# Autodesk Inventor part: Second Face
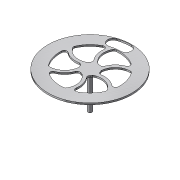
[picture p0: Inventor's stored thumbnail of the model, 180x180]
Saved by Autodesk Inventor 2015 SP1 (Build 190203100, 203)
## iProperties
Created: 2015-01
Part Number: Second Face
Material: Generic
Document SubType Name: Modeling
Designer: Steve Brooks
Density: 1 g/cm^3
Appearance: Machined - Aluminum
Author: Steve Brooks
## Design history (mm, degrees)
sketch "Sketch1"
  geometry: C1 r 7.5 at (203, 89); 1 further point
  constraints: 1 centre point
  dimensions: "d0" = 15 diameter of C1
extrude "Extrusion1" new body sketch "Sketch1" distance "d1" = 130; taper "d2" = 0 deg
sketch "Sketch2"
  geometry: C1 r 7.5 at (0, 0) reference; C2 r 155 at (0, 0); 1 further point
  constraints: 1 centre point, 1 coincident
  dimensions: "d3" = 310 diameter of C2
extrude "Extrusion2" join sketch "Sketch2" distance "d4" = 6; taper "d5" = 0 deg
sketch "Sketch3"
  geometry: L1 (0, 0)-(0, 133); L2 (0, 0)-(-41.099, 126.491); C1 r 155 at (0, 0) reference; C2 r 7.5 at (0, 0) reference; A1 r 20 centre (0, 133) between (0, 113) and (0, 153); A2 r 20 centre (-41.099, 126.491) between (-47.28, 145.512) and (-34.919, 107.469); A3 r 153 centre (0, 0) between (0, 153) and (-47.28, 145.512); A4 r 113 centre (0, 0) between (0, 113) and (-34.919, 107.469); 1 further point
  constraints: 8 point on circle, 4 centre point, 4 end point, 2 coincident, 2 point on line, 1 equal length, 1 vertical
  dimensions: "d8" = 40 diameter of A1; "d9" = 133 distance of C1.centre L1.end; "d19" = 40 diameter of A2; "d20" = 18 deg angle of L1 L2
extrude "Extrusion3" cut sketch "Sketch3" stored distance "d6" = 6; taper "d7" = 0 deg
sketch "Sketch4"
  geometry: C1 r 155 at (0, 0) reference; A1 r 67.599 centre (31.146, 78.451) between (-35.834, 87.575) and (-20.517, 34.857); A2 r 57.599 centre (31.146, 78.451) between (-20.621, 103.706) and (0, 30); A3 r 56.873 centre (-51.738, 65.706) between (-99.813, 35.32) and (-25.981, 15); A4 r 67.599 centre (-51.738, 65.706) between (-93.678, 12.691) and (-39.525, -0.78); A5 r 57.16 centre (-82.1, -11.374) between (-80.872, -68.521) and (-25.054, -14.967); A6 r 67.599 centre (-82.1, -11.374) between (-57.507, -74.34) and (-18.88, -35.308); A7 r 56.482 centre (-30.97, -77.234) between (18.946, -103.664) and (0, -30); A8 r 67.599 centre (-30.97, -77.234) between (35.856, -87.418) and (21.102, -34.129); A9 r 56.482 centre (51.401, -65.438) between (99.634, -36.049) and (25.981, -15); A10 r 67.599 centre (51.401, -65.438) between (93.635, -12.657) and (40.108, 1.211); A11 r 56.141 centre (82.023, 11.66) between (81.513, 67.799) and (25.981, 15); A12 r 67.599 centre (82.023, 11.66) between (57.733, 74.744) and (18.723, 35.381); A13 r 110 centre (0, 0) between (-50.316, 97.817) and (-100.495, 44.729); A14 r 30 centre (0, 0) between (-7.146, -29.136) and (0, -30); A15 r 30 centre (0, 0) between (21.604, -20.815) and (25.981, -15); A16 r 30 centre (0, 0) between (28.828, 8.303) and (25.981, 15); A17 r 30 centre (0, 0) between (7.019, 29.167) and (0, 30); A18 r 30 centre (0, 0) between (-21.12, 21.306) and (-25.981, 15); A19 r 29.184 centre (0, 0) between (-28.093, -7.907) and (-25.054, -14.967); A20 r 110 centre (0, 0) between (-109.871, 5.333) and (-89.195, -64.375); A21 r 109.499 centre (0, 0) between (-59.283, -92.063) and (11.124, -108.932); A22 r 110 centre (0, 0) between (50.316, -97.817) and (100.204, -45.377); A23 r 110 centre (0, 0) between (109.871, -5.333) and (89.764, 63.58); A24 r 110 centre (0, 0) between (59.554, 92.484) and (-12.796, 109.253); A25 r 10 centre (-53.869, -83.655) between (-57.507, -74.34) and (-59.283, -92.063); A26 r 10 centre (-99.882, 4.849) between (-93.678, 12.691) and (-109.871, 5.333); A27 r 10 centre (-45.742, 88.925) between (-35.834, 87.575) and (-50.316, 97.817); A28 r 10 centre (54.14, 84.076) between (57.733, 74.744) and (59.554, 92.484); A29 r 10 centre (99.882, -4.849) between (93.635, -12.657) and (109.871, -5.333); A30 r 10 centre (45.742, -88.925) between (35.856, -87.418) and (50.316, -97.817); A31 r 10 centre (-91.359, 40.663) between (-100.495, 44.729) and (-99.813, 35.32); A32 r 10 centre (-28.16, 28.408) between (-21.12, 21.306) and (-20.517, 34.857); A33 r 10 centre (9.358, 38.89) between (7.019, 29.167) and (18.723, 35.381); A34 r 10 centre (38.438, 11.07) between (28.828, 8.303) and (40.108, 1.211); A35 r 10 centre (28.806, -27.753) between (21.604, -20.815) and (21.102, -34.129); A36 r 10 centre (-9.528, -38.849) between (-7.146, -29.136) and (-18.88, -35.308); A37 r 10 centre (-37.719, -10.616) between (-28.093, -7.907) and (-39.525, -0.78); A38 r 10 centre (10.108, -98.984) between (11.124, -108.932) and (18.946, -103.664); A39 r 10 centre (91.095, -41.252) between (100.204, -45.377) and (99.634, -36.049); A40 r 10 centre (-81.087, -58.523) between (-89.195, -64.375) and (-80.872, -68.521); A41 r 10 centre (-11.633, 99.321) between (-12.796, 109.253) and (-20.621, 103.706); A42 r 10 centre (81.604, 57.8) between (89.764, 63.58) and (81.513, 67.799); 1 further point
  constraints: 84 point on circle, 42 centre point, 36 tangent, 30 equal radius, 2 coincident, 1 vertical alignment
  dimensions: "d10" = 10 radial gap between concentric circles of A1 A2; "d14" = 10 radius of A25; "d15" = 30 radius of A17; "d16" = 110 radius of A24
extrude "Extrusion4" cut sketch "Sketch4" stored distance "d17" = 6; taper "d18" = 0 deg
body "Solid1"
